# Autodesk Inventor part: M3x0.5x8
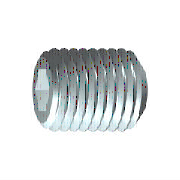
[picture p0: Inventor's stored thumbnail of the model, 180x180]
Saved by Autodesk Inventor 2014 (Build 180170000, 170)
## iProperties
IsCustomPart: 1
Company: 한국ATC센터
Created: 2009-02
Part Number: M3x0.5x8
Material: 강, 연강
Description: 6각 소켓 머리 없는 멈춤 나사
Document SubType Name: Modeling
Standard: KS B 1028
Designer: KYOUNG IL JANG
Standards Organization: KS
Language: ko-KR
Size Designation: 납작점M3x6
Categories: <MemberInstance><Categories><Category DisplayName="조임쇠" InternalName="e4da775c-781d-43d5-af7c-5136215cf5a6" Mnemonic="FSTN"><Category DisplayName="볼트" InternalN
Density: 7.86 g/cm^3
Mass: 0.293227 g
Surface Area: 0.779768 cm^2
Volume: 0.0373062 cm^3
Vendor: CBT Solutions
Appearance: 강철
Author: KYOUNG IL JANG
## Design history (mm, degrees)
sketch "스케치1"
  geometry: L1 (0, 0)-(3.5, 0); L2 (6, 0.866)-(6, 1.5); L3 (6, 1.5)-(0, 1.5); L4 (6, 0.866)-(4, 0.866); L5 (4, 0.866)-(3.5, 0); L6 (0, -0.3)-(0, 1.8) reference; L7 (0, 1.5)-(0, 0)
  constraints: 13 end point, 3 parallel, 1 collinear, 1 perpendicular, 1 point on line
  dimensions: "d0" = 2 distance of L2.start L4.end (= INTI); "d1" = 60 deg angle of L5 L1; "d2" = 3 diameter of L3 L1 (= NND); "d3" = 1.73205 diameter of L4 L1 (= 1.1547 x SW); "d5" = 6 distance from line of L2 L3.end (= NLG)
revolve "본체" sketch "스케치1" stored, may be unused: angle "d6" = 90 deg
sketch "스케치2"
  geometry: L1 (-0.433, 0.75)-(0.433, 0.75); L2 (0.433, 0.75)-(0.866, 0); L3 (0.866, 0)-(0.433, -0.75); L4 (0.433, -0.75)-(-0.433, -0.75); L5 (-0.433, -0.75)-(-0.866, 0); L6 (-0.866, 0)-(-0.433, 0.75); A1 r 0.866 centre (0, 0) between (-0.433, 0.75) and (0.433, 0.75) reference; 2 further points
  constraints: 12 end point, 2 point on circle, 1 coincident, 1 horizontal, 11 other
extrude "슬롯" join sketch "스케치2" taper "d9" = 0 deg; stored distance "d21" = 10
workaxis "Work Axis1"
workplane "Work Plane1"
body "Solid1"
chamfer "모따기1" distance "d7" = 0.30673 (= -0.5 x GD1 + 0.5 x NND); stored, may be unused: angle "d8" = 45 deg (= FAWI), second distance "d29" = 0.30673 (= -0.5 x GD1 + 0.5 x NND)
feature "스레드" dims "d11" = 6 (= NLG), "d12" = 0
chamfer "모따기2" distance "d13" = 0.30673 (= -0.5 x GD1 + 0.5 x NND); stored, may be unused: angle "d14" = 45 deg (= FAWI), second distance "d30" = 0.30673 (= -0.5 x GD1 + 0.5 x NND)
other parameters: "NND" = 3 [user parameter; used in 5 equation terms], "NLG" = 6 [user parameter; used in 2 equation terms], "INTI" = 2 [user parameter; used in 1 equation term], "FAWI" = 45 deg [user parameter; used in 2 equation terms], "SW" = 1.5 [user parameter; used in 2 equation terms], "GD1" = 2.38655 (= THREADDIA - 1.2269 x PTC) [user parameter; used in 4 equation terms], "d4" = 0, "FAWI1" = 45 deg [user parameter], "d15" = 0, "d31" = 0, "GUL" = 0.30673 (= 0.61345 x PTC) [user parameter], "SPD" = 2 [user parameter], "TOA" = 30 deg [user parameter], "THREADDIA" = 3 [user parameter; used in 1 equation term], "PTC" = 0.5 [user parameter; used in 4 equation terms], "GAL" = 0.30673 (= 0.61345 x PTC) [user parameter], "E0" = 1.7325 (= 1.155 x SW) [user parameter]
